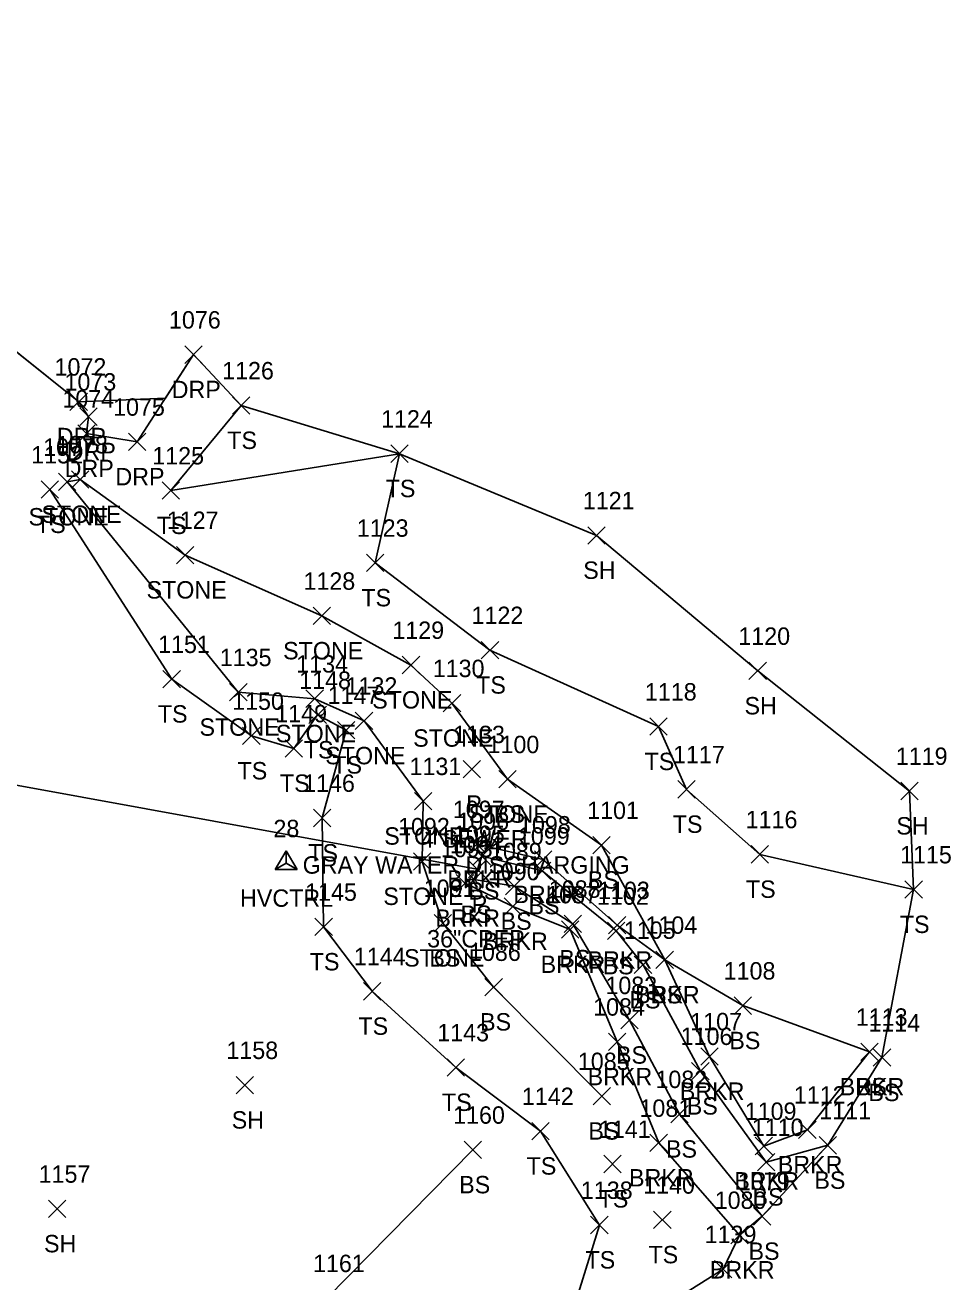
# Model space of a CAD drawing. Extents: x 1639430 to 1640195, y 612006 to 612917.
# Drawn here: x 1640088.8 to 1640195.2, y 612501.1 to 612645.5 of the extents above; entities that cross this region are included whole.
import ezdxf

# ---------------------------------------------------------------- set-up
doc = ezdxf.new("R2010")
doc.units = 0
for name, color, linetype in [('C_A', 7, 'Continuous'), ('C_I', 7, 'Continuous'), ('CPSM', 7, 'Continuous'), ('D_A', 7, 'Continuous'), ('D_C', 7, 'Continuous'), ('D_I', 7, 'Continuous'), ('D_TIC', 7, 'Continuous'), ('DCP', 7, 'Continuous'), ('L_A', 7, 'Continuous'), ('L_I', 7, 'Continuous'), ('L_TIC', 7, 'Continuous'), ('LASF', 7, 'Continuous'), ('LAWA', 7, 'Continuous'), ('LAWE', 7, 'Continuous'), ('LELB', 7, 'Continuous'), ('LSOGP', 7, 'Continuous'), ('R_A', 7, 'Continuous'), ('R_I', 7, 'Continuous'), ('R_TIC', 7, 'Continuous'), ('RDP', 7, 'Continuous')]:
    doc.layers.add(name, color=color, linetype=linetype)

msp = doc.modelspace()

# ---------------------------------------------------------------- linework, layer by layer
at = {"layer": 'CPSM'}
for p, q in [((1640117.53, 612548.48), (1640118.78, 612550.65)), ((1640120.03, 612548.48), (1640118.78, 612550.65)), ((1640118.79, 612549.2), (1640118.78, 612550.65)), ((1640117.53, 612548.48), (1640118.79, 612549.2)), ((1640117.53, 612548.48), (1640120.03, 612548.48)), ((1640118.79, 612549.2), (1640118.79, 612549.2)), ((1640118.79, 612549.2), (1640120.03, 612548.48))]:
    msp.add_line(p, q, dxfattribs=at)
at = {"layer": 'D_TIC'}
for points in [[(1640139.11, 612559.01), (1640141.11, 612561.01)], [(1640141.11, 612559.01), (1640139.11, 612561.01)], [(1640139.73, 612547.53), (1640141.73, 612549.53)], [(1640141.73, 612547.53), (1640139.73, 612549.53)]]:
    msp.add_lwpolyline(points, dxfattribs=at)
at = {"layer": 'DCP'}
msp.add_lwpolyline([(1639875.64, 612596.85), (1640140.73, 612548.53)], dxfattribs=at)
at = {"layer": 'L_TIC'}
for points in [[(1640112.6, 612600.82), (1640114.6, 612602.82)], [(1640114.6, 612600.82), (1640112.6, 612602.82)], [(1640130.81, 612595.28), (1640132.81, 612597.28)], [(1640132.81, 612595.28), (1640130.81, 612597.28)], [(1640094.11, 612592.32), (1640096.11, 612594.32)], [(1640096.11, 612592.32), (1640094.11, 612594.32)], [(1640090.61, 612591.16), (1640092.61, 612593.16)], [(1640092.61, 612591.16), (1640090.61, 612593.16)], [(1640092.62, 612592.03), (1640094.62, 612594.03)], [(1640094.62, 612592.03), (1640092.62, 612594.03)], [(1640092.62, 612592.03), (1640094.62, 612594.03)], [(1640094.62, 612592.03), (1640092.62, 612594.03)], [(1640104.51, 612591.04), (1640106.51, 612593.04)], [(1640106.51, 612591.04), (1640104.51, 612593.04)], [(1640153.44, 612585.89), (1640155.44, 612587.89)], [(1640155.44, 612585.89), (1640153.44, 612587.89)], [(1640106.18, 612583.63), (1640108.18, 612585.63)], [(1640108.18, 612583.63), (1640106.18, 612585.63)], [(1640128.02, 612582.73), (1640130.02, 612584.73)], [(1640130.02, 612582.73), (1640128.02, 612584.73)], [(1640121.89, 612576.64), (1640123.89, 612578.64)], [(1640123.89, 612576.64), (1640121.89, 612578.64)], [(1640141.21, 612572.7), (1640143.21, 612574.7)], [(1640143.21, 612572.7), (1640141.21, 612574.7)], [(1640132.13, 612570.99), (1640134.13, 612572.99)], [(1640134.13, 612570.99), (1640132.13, 612572.99)], [(1640104.62, 612569.37), (1640106.62, 612571.37)], [(1640106.62, 612569.37), (1640104.62, 612571.37)], [(1640171.98, 612570.31), (1640173.98, 612572.31)], [(1640173.98, 612570.31), (1640171.98, 612572.31)], [(1640112.28, 612567.86), (1640114.28, 612569.86)], [(1640114.28, 612567.86), (1640112.28, 612569.86)], [(1640112.28, 612567.86), (1640114.28, 612569.86)], [(1640114.28, 612567.86), (1640112.28, 612569.86)], [(1640121.06, 612567.12), (1640123.06, 612569.12)], [(1640123.06, 612567.12), (1640121.06, 612569.12)], [(1640136.84, 612566.6), (1640138.84, 612568.6)], [(1640138.84, 612566.6), (1640136.84, 612568.6)], [(1640136.84, 612566.6), (1640138.84, 612568.6)], [(1640138.84, 612566.6), (1640136.84, 612568.6)], [(1640121.4, 612565.25), (1640123.4, 612567.25)], [(1640123.4, 612565.25), (1640121.4, 612567.25)], [(1640124.68, 612563.51), (1640126.68, 612565.51)], [(1640126.68, 612563.51), (1640124.68, 612565.51)], [(1640126.73, 612564.58), (1640128.73, 612566.58)], [(1640128.73, 612564.58), (1640126.73, 612566.58)], [(1640160.57, 612563.91), (1640162.57, 612565.91)], [(1640162.57, 612563.91), (1640160.57, 612565.91)], [(1640113.78, 612562.84), (1640115.78, 612564.84)], [(1640115.78, 612562.84), (1640113.78, 612564.84)], [(1640118.66, 612561.41), (1640120.66, 612563.41)], [(1640120.66, 612561.41), (1640118.66, 612563.41)], [(1640143.22, 612557.86), (1640145.22, 612559.86)], [(1640145.22, 612557.86), (1640143.22, 612559.86)], [(1640143.22, 612557.86), (1640145.22, 612559.86)], [(1640145.22, 612557.86), (1640143.22, 612559.86)], [(1640163.81, 612556.7), (1640165.81, 612558.7)], [(1640165.81, 612556.7), (1640163.81, 612558.7)], [(1640189.43, 612556.51), (1640191.43, 612558.51)], [(1640191.43, 612556.51), (1640189.43, 612558.51)], [(1640133.52, 612555.34), (1640135.52, 612557.34)], [(1640135.52, 612555.34), (1640133.52, 612557.34)], [(1640121.91, 612553.41), (1640123.91, 612555.41)], [(1640123.91, 612553.41), (1640121.91, 612555.41)], [(1640139.71, 612550.4), (1640141.71, 612552.4)], [(1640141.71, 612550.4), (1640139.71, 612552.4)], [(1640140.28, 612549.03), (1640142.28, 612551.03)], [(1640142.28, 612549.03), (1640140.28, 612551.03)], [(1640154.02, 612550.29), (1640156.02, 612552.29)], [(1640156.02, 612550.29), (1640154.02, 612552.29)], [(1640172.22, 612549.23), (1640174.22, 612551.23)], [(1640174.22, 612549.23), (1640172.22, 612551.23)], [(1640133.41, 612548.41), (1640135.41, 612550.41)], [(1640135.41, 612548.41), (1640133.41, 612550.41)], [(1640147.31, 612548.63), (1640149.31, 612550.63)], [(1640149.31, 612548.63), (1640147.31, 612550.63)], [(1640139.39, 612546.35), (1640141.39, 612548.35)], [(1640141.39, 612546.35), (1640139.39, 612548.35)], [(1640147.2, 612547.34), (1640149.2, 612549.34)], [(1640149.2, 612547.34), (1640147.2, 612549.34)], [(1640138.34, 612545.9), (1640140.34, 612547.9)], [(1640140.34, 612545.9), (1640138.34, 612547.9)], [(1640143.99, 612545.56), (1640145.99, 612547.56)], [(1640145.99, 612545.56), (1640143.99, 612547.56)], [(1640189.91, 612545.19), (1640191.91, 612547.19)], [(1640191.91, 612545.19), (1640189.91, 612547.19)], [(1640143.83, 612543.25), (1640145.83, 612545.25)], [(1640145.83, 612543.25), (1640143.83, 612545.25)], [(1640122.09, 612540.89), (1640124.09, 612542.89)], [(1640124.09, 612540.89), (1640122.09, 612542.89)], [(1640135.8, 612541.33), (1640137.8, 612543.33)], [(1640137.8, 612541.33), (1640135.8, 612543.33)], [(1640135.8, 612541.33), (1640137.8, 612543.33)], [(1640137.8, 612541.33), (1640135.8, 612543.33)], [(1640150.44, 612540.6), (1640152.44, 612542.6)], [(1640152.44, 612540.6), (1640150.44, 612542.6)], [(1640150.74, 612541.24), (1640152.74, 612543.24)], [(1640152.74, 612541.24), (1640150.74, 612543.24)], [(1640155.72, 612540.44), (1640157.72, 612542.44)], [(1640157.72, 612540.44), (1640155.72, 612542.44)], [(1640155.83, 612541.09), (1640157.83, 612543.09)], [(1640157.83, 612541.09), (1640155.83, 612543.09)], [(1640158.8, 612536.52), (1640160.8, 612538.52)], [(1640160.8, 612536.52), (1640158.8, 612538.52)], [(1640161.29, 612537.1), (1640163.29, 612539.1)], [(1640163.29, 612537.1), (1640161.29, 612539.1)], [(1640161.29, 612537.1), (1640163.29, 612539.1)], [(1640163.29, 612537.1), (1640161.29, 612539.1)], [(1640127.68, 612533.49), (1640129.68, 612535.49)], [(1640129.68, 612533.49), (1640127.68, 612535.49)], [(1640141.63, 612533.98), (1640143.63, 612535.98)], [(1640143.63, 612533.98), (1640141.63, 612535.98)], [(1640170.28, 612531.84), (1640172.28, 612533.84)], [(1640172.28, 612531.84), (1640170.28, 612533.84)], [(1640157.25, 612530.17), (1640159.25, 612532.17)], [(1640159.25, 612530.17), (1640157.25, 612532.17)], [(1640155.84, 612527.69), (1640157.84, 612529.69)], [(1640157.84, 612527.69), (1640155.84, 612529.69)], [(1640166.44, 612526.01), (1640168.44, 612528.01)], [(1640168.44, 612526.01), (1640166.44, 612528.01)], [(1640184.82, 612526.53), (1640186.82, 612528.53)], [(1640186.82, 612526.53), (1640184.82, 612528.53)], [(1640184.82, 612526.53), (1640186.82, 612528.53)], [(1640186.82, 612526.53), (1640184.82, 612528.53)], [(1640186.27, 612525.87), (1640188.27, 612527.87)], [(1640188.27, 612525.87), (1640186.27, 612527.87)], [(1640137.28, 612524.74), (1640139.28, 612526.74)], [(1640139.28, 612524.74), (1640137.28, 612526.74)], [(1640165.39, 612524.32), (1640167.39, 612526.32)], [(1640167.39, 612524.32), (1640165.39, 612526.32)], [(1640113.03, 612522.71), (1640115.03, 612524.71)], [(1640115.03, 612522.71), (1640113.03, 612524.71)], [(1640154.08, 612521.44), (1640156.08, 612523.44)], [(1640156.08, 612521.44), (1640154.08, 612523.44)], [(1640163, 612519.37), (1640165, 612521.37)], [(1640165, 612519.37), (1640163, 612521.37)], [(1640147.01, 612517.42), (1640149.01, 612519.42)], [(1640149.01, 612517.42), (1640147.01, 612519.42)], [(1640147.01, 612517.42), (1640149.01, 612519.42)], [(1640149.01, 612517.42), (1640147.01, 612519.42)], [(1640177.69, 612517.58), (1640179.69, 612519.58)], [(1640179.69, 612517.58), (1640177.69, 612519.58)], [(1640160.6, 612516.06), (1640162.6, 612518.06)], [(1640162.6, 612516.06), (1640160.6, 612518.06)], [(1640180.06, 612515.79), (1640182.06, 612517.79)], [(1640182.06, 612515.79), (1640180.06, 612517.79)], [(1640139.23, 612515.27), (1640141.23, 612517.27)], [(1640141.23, 612515.27), (1640139.23, 612517.27)], [(1640172.7, 612515.71), (1640174.7, 612517.71)], [(1640174.7, 612515.71), (1640172.7, 612517.71)], [(1640155.29, 612513.64), (1640157.29, 612515.64)], [(1640157.29, 612513.64), (1640155.29, 612515.64)], [(1640172.95, 612513.86), (1640174.95, 612515.86)], [(1640174.95, 612513.86), (1640172.95, 612515.86)], [(1640091.46, 612508.49), (1640093.46, 612510.49)], [(1640093.46, 612508.49), (1640091.46, 612510.49)], [(1640161.02, 612507.23), (1640163.02, 612509.23)], [(1640163.02, 612507.23), (1640161.02, 612509.23)], [(1640172.49, 612507.63), (1640174.49, 612509.63)], [(1640174.49, 612507.63), (1640172.49, 612509.63)], [(1640153.78, 612506.63), (1640155.78, 612508.63)], [(1640155.78, 612506.63), (1640153.78, 612508.63)], [(1640169.9, 612505.48), (1640171.9, 612507.48)], [(1640171.9, 612505.48), (1640169.9, 612507.48)], [(1640168.02, 612501.55), (1640170.02, 612503.55)], [(1640170.02, 612501.55), (1640168.02, 612503.55)], [(1640168.02, 612501.55), (1640170.02, 612503.55)], [(1640170.02, 612501.55), (1640168.02, 612503.55)]]:
    msp.add_lwpolyline(points, dxfattribs=at)
at = {"layer": 'LASF'}
for points in [[(1640093.62, 612593.03), (1640095.11, 612593.32), (1640107.18, 612584.63), (1640122.89, 612577.64), (1640133.13, 612571.99), (1640137.84, 612567.6)], [(1640093.62, 612593.03), (1640113.28, 612568.86)], [(1640136.8, 612542.33), (1640134.41, 612549.41), (1640134.52, 612556.34), (1640127.73, 612565.58), (1640122.06, 612568.12), (1640113.28, 612568.86)], [(1640144.22, 612558.86), (1640137.84, 612567.6)]]:
    msp.add_lwpolyline(points, dxfattribs=at)
at = {"layer": 'LAWA'}
msp.add_lwpolyline([(1640126.63, 612406.13), (1640137.15, 612457.44), (1640141.89, 612470.54), (1640153.39, 612491.92), (1640154, 612493.09), (1640169.02, 612502.55)], dxfattribs=at)
at = {"layer": 'LAWE'}
for points in [[(1640140.71, 612551.4), (1640148.31, 612549.63), (1640156.83, 612542.09), (1640162.29, 612538.1), (1640167.44, 612527.01), (1640173.7, 612516.71), (1640178.69, 612518.58), (1640185.82, 612527.53)], [(1640170.9, 612506.48), (1640161.6, 612517.06), (1640156.84, 612528.69), (1640151.44, 612541.6), (1640144.83, 612544.25), (1640139.34, 612546.9)]]:
    msp.add_lwpolyline(points, dxfattribs=at)
at = {"layer": 'LELB'}
for points in [[(1640190.91, 612546.19), (1640173.22, 612550.23), (1640164.81, 612557.7), (1640161.57, 612564.91), (1640142.21, 612573.7), (1640129.02, 612583.73), (1640131.81, 612596.28), (1640105.51, 612592.04), (1640113.6, 612601.82)], [(1640141.89, 612470.54), (1640144.93, 612487.52), (1640150.93, 612495.15), (1640150.98, 612495.27), (1640154.78, 612507.63), (1640148.01, 612518.42), (1640138.28, 612525.74), (1640128.68, 612534.49), (1640123.09, 612541.89), (1640122.91, 612554.41), (1640125.68, 612564.51), (1640122.4, 612566.25), (1640119.66, 612562.41), (1640114.78, 612563.84), (1640105.62, 612570.37), (1640091.61, 612592.16)], [(1640144.22, 612558.86), (1640155.02, 612551.29), (1640162.29, 612538.1), (1640171.28, 612532.84), (1640185.82, 612527.53)], [(1640173.49, 612508.63), (1640164, 612520.37), (1640158.25, 612531.17), (1640151.74, 612542.24), (1640144.99, 612546.56), (1640140.39, 612547.35), (1640141.28, 612550.03), (1640148.2, 612548.34), (1640156.72, 612541.44), (1640159.8, 612537.52), (1640166.39, 612525.32), (1640173.95, 612514.86), (1640181.06, 612516.79), (1640187.27, 612526.87)], [(1640155.08, 612522.44), (1640142.63, 612534.98), (1640136.8, 612542.33)], [(1640140.23, 612516.27), (1640123.47, 612499.22), (1640117.6, 612483.99), (1640116.42, 612461.14), (1640113.26, 612432.2), (1640089.7, 612438.66), (1640054.14, 612454.58), (1640026.5, 612472.2), (1639999.71, 612491.99), (1639981.61, 612510.09)]]:
    msp.add_lwpolyline(points, dxfattribs=at)
at = {"layer": 'LSOGP'}
msp.add_lwpolyline([(1640154, 612493.09), (1640169.02, 612502.55), (1640170.9, 612506.48), (1640173.49, 612508.63), (1640181.06, 612516.79), (1640187.27, 612526.87), (1640190.91, 612546.19), (1640190.43, 612557.51), (1640172.98, 612571.31), (1640154.44, 612586.89), (1640131.81, 612596.28), (1640113.6, 612601.82), (1640108.13, 612607.66), (1640104.9, 612602.65), (1640094.93, 612602.25), (1640089.79, 612606.37), (1640084.65, 612610.49)], dxfattribs=at)
at = {"layer": 'R_TIC'}
for points in [[(1640107.13, 612606.66), (1640109.13, 612608.66)], [(1640109.13, 612606.66), (1640107.13, 612608.66)], [(1640093.93, 612601.25), (1640095.93, 612603.25)], [(1640095.93, 612601.25), (1640093.93, 612603.25)], [(1640095.07, 612599.53), (1640097.07, 612601.53)], [(1640097.07, 612599.53), (1640095.07, 612601.53)], [(1640094.84, 612597.58), (1640096.84, 612599.58)], [(1640096.84, 612597.58), (1640094.84, 612599.58)], [(1640100.66, 612596.64), (1640102.66, 612598.64)], [(1640102.66, 612596.64), (1640100.66, 612598.64)]]:
    msp.add_lwpolyline(points, dxfattribs=at)
at = {"layer": 'RDP'}
msp.add_lwpolyline([(1639965.19, 612645.53), (1639979.17, 612644.84), (1640018.38, 612633.31), (1640049.07, 612624.59), (1640074.87, 612616.7), (1640084.65, 612610.49), (1640094.93, 612602.25), (1640096.07, 612600.53), (1640095.84, 612598.58), (1640101.66, 612597.64), (1640108.13, 612607.66)], dxfattribs=at)

# ---------------------------------------------------------------- texts
at = {"layer": 'C_A'}
msp.add_text('HVCTRL', height=2, dxfattribs=at).set_placement((1640113.48, 612544.2))
at = {"layer": 'C_I'}
msp.add_text('28', height=2, dxfattribs=at).set_placement((1640117.32, 612552.2))
at = {"layer": 'D_A'}
for p in [(1640139.48, 612555.01), (1640140.11, 612543.53)]:
    msp.add_text('P', height=2, dxfattribs=at).set_placement(p)
at = {"layer": 'D_C'}
for s, p in [('4"SEWER', (1640134.29, 612551.01)), ('GRAY WATER DISCHARGING', (1640120.68, 612548.01)), ('36"CPEP', (1640134.99, 612539.53))]:
    msp.add_text(s, height=2, dxfattribs=at).set_placement(p)
at = {"layer": 'D_I'}
for s, p in [('1133', (1640137.98, 612563.01)), ('1095', (1640137.96, 612551.53))]:
    msp.add_text(s, height=2, dxfattribs=at).set_placement(p)
at = {"layer": 'L_A'}
for s, p in [('TS', (1640112.01, 612596.82)), ('TS', (1640130.22, 612591.28)), ('STONE', (1640089.17, 612588.03)), ('STONE', (1640089.17, 612588.03)), ('STONE', (1640090.65, 612588.32)), ('TS', (1640090.02, 612587.16)), ('TS', (1640103.92, 612587.04)), ('SH', (1640152.93, 612581.89)), ('STONE', (1640102.73, 612579.63)), ('TS', (1640127.43, 612578.73)), ('STONE', (1640118.43, 612572.64)), ('TS', (1640140.62, 612568.7)), ('STONE', (1640128.67, 612566.99)), ('SH', (1640171.47, 612566.31)), ('TS', (1640104.03, 612565.37)), ('STONE', (1640108.82, 612563.86)), ('STONE', (1640108.82, 612563.86)), ('STONE', (1640117.6, 612563.12)), ('STONE', (1640133.38, 612562.6)), ('STONE', (1640133.38, 612562.6)), ('TS', (1640120.81, 612561.25)), ('STONE', (1640123.28, 612560.58)), ('TS', (1640124.09, 612559.51)), ('TS', (1640159.98, 612559.91)), ('TS', (1640113.19, 612558.84)), ('TS', (1640118.07, 612557.41)), ('STONE', (1640139.76, 612553.86)), ('BS', (1640142.66, 612553.86)), ('TS', (1640163.22, 612552.7)), ('SH', (1640188.92, 612552.51)), ('STONE', (1640130.06, 612551.34)), ('TS', (1640121.32, 612549.41)), ('BRKR', (1640137.3, 612546.4)), ('BS', (1640153.46, 612546.29)), ('BS', (1640139.72, 612545.03)), ('BRKR', (1640144.9, 612544.63)), ('TS', (1640171.63, 612545.23)), ('STONE', (1640129.95, 612544.41)), ('BS', (1640146.64, 612543.34)), ('BRKR', (1640135.93, 612541.9)), ('BS', (1640138.83, 612542.35)), ('BS', (1640143.43, 612541.56)), ('TS', (1640189.32, 612541.19)), ('BRKR', (1640141.42, 612539.25)), ('TS', (1640121.49, 612536.89)), ('STONE', (1640132.34, 612537.33)), ('BS', (1640135.24, 612537.33)), ('BRKR', (1640148.03, 612536.6)), ('BS', (1640150.18, 612537.24)), ('BRKR', (1640153.42, 612537.09)), ('BS', (1640155.16, 612536.44)), ('BRKR', (1640158.88, 612533.1)), ('BS', (1640160.73, 612533.1)), ('BS', (1640158.24, 612532.52)), ('TS', (1640127.09, 612529.49)), ('BS', (1640141.07, 612529.98)), ('BS', (1640169.72, 612527.84)), ('BS', (1640156.69, 612526.17)), ('BRKR', (1640153.43, 612523.69)), ('BRKR', (1640164.03, 612522.01)), ('BRKR', (1640182.41, 612522.53)), ('BS', (1640184.26, 612522.53)), ('BS', (1640185.71, 612521.87)), ('TS', (1640136.69, 612520.74)), ('BS', (1640164.83, 612520.32)), ('SH', (1640112.52, 612518.71)), ('BS', (1640153.52, 612517.44)), ('BS', (1640162.44, 612515.37)), ('TS', (1640146.42, 612513.42)), ('TS', (1640146.42, 612513.42)), ('BRKR', (1640175.29, 612513.58)), ('BRKR', (1640158.19, 612512.06)), ('BRKR', (1640170.29, 612511.71)), ('BS', (1640179.5, 612511.79)), ('BS', (1640138.67, 612511.27)), ('TS', (1640154.7, 612509.64)), ('BS', (1640172.39, 612509.86)), ('SH', (1640090.95, 612504.49)), ('TS', (1640160.43, 612503.23)), ('BS', (1640171.93, 612503.63)), ('TS', (1640153.19, 612502.63)), ('BRKR', (1640167.49, 612501.48))]:
    msp.add_text(s, height=2, dxfattribs=at).set_placement(p)
at = {"layer": 'L_I'}
for s, p in [('1126', (1640111.42, 612604.82)), ('1124', (1640129.69, 612599.28)), ('1152', (1640089.48, 612595.16)), ('1077', (1640090.85, 612596.03)), ('1077', (1640090.85, 612596.03)), ('1078', (1640092.34, 612596.32)), ('1125', (1640103.39, 612595.04)), ('1121', (1640152.88, 612589.89)), ('1127', (1640105.06, 612587.63)), ('1123', (1640126.9, 612586.73)), ('1128', (1640120.77, 612580.64)), ('1122', (1640140.09, 612576.7)), ('1129', (1640130.99, 612574.99)), ('1120', (1640170.76, 612574.31)), ('1151', (1640104.06, 612573.37)), ('1135', (1640111.15, 612571.86)), ('1135', (1640111.15, 612571.86)), ('1134', (1640119.94, 612571.12)), ('1148', (1640120.28, 612569.25)), ('1130', (1640135.63, 612570.6)), ('1130', (1640135.63, 612570.6)), ('1132', (1640125.61, 612568.58)), ('1118', (1640160.02, 612567.91)), ('1150', (1640112.57, 612566.84)), ('1147', (1640123.55, 612567.51)), ('1149', (1640117.53, 612565.41)), ('1100', (1640141.93, 612561.86)), ('1100', (1640141.93, 612561.86)), ('1117', (1640163.25, 612560.7)), ('1119', (1640188.86, 612560.51)), ('1131', (1640132.96, 612559.34)), ('1146', (1640120.73, 612557.41)), ('1097', (1640137.94, 612554.4)), ('1101', (1640153.38, 612554.29)), ('1092', (1640131.64, 612552.41)), ('1096', (1640138.45, 612553.03)), ('1098', (1640145.54, 612552.63)), ('1116', (1640171.6, 612553.23)), ('1099', (1640145.42, 612551.34)), ('1093', (1640136.57, 612549.9)), ('1094', (1640137.62, 612550.35)), ('1089', (1640142.21, 612549.56)), ('1115', (1640189.35, 612549.19)), ('1090', (1640141.97, 612547.25)), ('1145', (1640120.96, 612544.89)), ('1091', (1640134.59, 612545.33)), ('1091', (1640134.59, 612545.33)), ('1087', (1640148.67, 612544.6)), ('1088', (1640148.97, 612545.24)), ('1103', (1640154.63, 612545.09)), ('1102', (1640154.51, 612544.44)), ('1105', (1640157.6, 612540.52)), ('1104', (1640160.08, 612541.1)), ('1104', (1640160.08, 612541.1)), ('1144', (1640126.56, 612537.49)), ('1086', (1640139.8, 612537.98)), ('1108', (1640169.07, 612535.84)), ('1083', (1640155.48, 612534.17)), ('1084', (1640154.07, 612531.69)), ('1113', (1640184.26, 612530.53)), ('1113', (1640184.26, 612530.53)), ('1143', (1640136.15, 612528.74)), ('1107', (1640165.23, 612530.01)), ('1114', (1640185.71, 612529.87)), ('1106', (1640164.13, 612528.32)), ('1158', (1640111.91, 612526.71)), ('1085', (1640152.31, 612525.44)), ('1082', (1640161.23, 612523.37)), ('1112', (1640177.14, 612521.58)), ('1142', (1640145.88, 612521.42)), ('1142', (1640145.88, 612521.42)), ('1081', (1640159.39, 612520.06)), ('1160', (1640137.97, 612519.27)), ('1109', (1640171.49, 612519.71)), ('1111', (1640180.07, 612519.79)), ('1141', (1640154.73, 612517.64)), ('1110', (1640172.3, 612517.86)), ('1157', (1640090.33, 612512.49)), ('1079', (1640170.71, 612511.63)), ('1138', (1640152.66, 612510.63)), ('1140', (1640159.81, 612511.23)), ('1080', (1640168.04, 612509.48)), ('1139', (1640166.89, 612505.55)), ('1139', (1640166.89, 612505.55)), ('1161', (1640121.87, 612502.22))]:
    msp.add_text(s, height=2, dxfattribs=at).set_placement(p)
at = {"layer": 'R_A'}
for p in [(1640105.62, 612602.66), (1640092.42, 612597.25), (1640093.56, 612595.53), (1640093.32, 612593.58), (1640099.15, 612592.64)]:
    msp.add_text('DRP', height=2, dxfattribs=at).set_placement(p)
at = {"layer": 'R_I'}
for s, p in [('1076', (1640105.31, 612610.66)), ('1072', (1640092.16, 612605.25)), ('1073', (1640093.3, 612603.53)), ('1074', (1640093.06, 612601.58)), ('1075', (1640098.89, 612600.64))]:
    msp.add_text(s, height=2, dxfattribs=at).set_placement(p)

doc.saveas('drawing.dxf')
